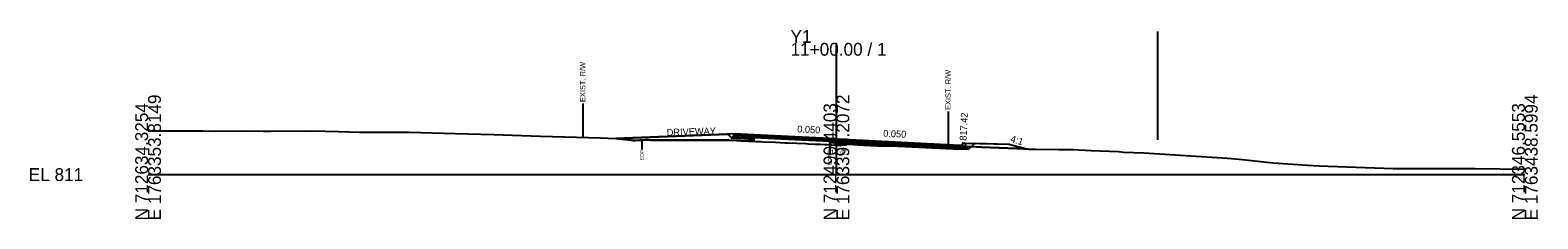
# Model space of a CAD drawing. Extents: x -26 to 1303, y -10 to 9524.
# Drawn here: x -25.7 to 302.8, y 990.3 to 1031.6 of the extents above; entities that cross this region are included whole.
import ezdxf

# ---------------------------------------------------------------- set-up
doc = ezdxf.new("R2010")
doc.units = 0
for name, color, linetype in [('Default', 7, 'Continuous'), ('Exist CMT Pavement', 7, 'Continuous'), ('Exist Cross Section Cell', 7, 'Continuous'), ('Exist XS Center Line Elevation Label', 7, 'Continuous'), ('Exist XS Ground Line', 7, 'Continuous'), ('Old_Level_10', 7, 'Continuous'), ('Prop CMT Conc Surface', 7, 'Continuous'), ('Prop CMT Concrete Structures', 7, 'Continuous'), ('Prop CMT Pvmt Course 1', 7, 'Continuous'), ('Prop CMT Pvmt Course 1 CG', 7, 'Continuous'), ('Prop CMT Pvmt Course 2', 7, 'Continuous'), ('Prop CMT Pvmt Course 3', 7, 'Continuous'), ('Prop CMT Pvmt Surface', 7, 'Continuous'), ('Prop CMT Pvmt Surface Shoulder', 7, 'Continuous'), ('Prop CMT Shld Paved Course 1', 7, 'Continuous'), ('Prop CMT Shld Paved Course 3', 7, 'Continuous'), ('Prop CMT Slope Grass', 7, 'Continuous'), ('Prop CMT Subgrade Earthwork', 7, 'Continuous'), ('Prop XS Earthwork Shape', 7, 'Continuous'), ('Prop XS Hydro Elevations', 7, 'Continuous'), ('Prop XS SE Text', 7, 'Continuous'), ('Prop XS Side Slope Text', 7, 'Continuous'), ('Prop XS Wedging', 7, 'Continuous')]:
    doc.layers.add(name, color=color, linetype=linetype)

msp = doc.modelspace()

# ---------------------------------------------------------------- linework, layer by layer
at = {"layer": 'Exist CMT Pavement'}
msp.add_lwpolyline([(131.98, 1007.27), (132.46, 1007.25), (133.52, 1007.19), (133.96, 1007.18), (136.69, 1007.08), (138.73, 1006.96), (139.32, 1006.93), (141.34, 1006.86), (143.34, 1006.76), (143.94, 1006.73), (145.36, 1006.67), (146.55, 1006.61), (147.47, 1006.56), (147.96, 1006.54), (148.58, 1006.5)], dxfattribs=at)
at = {"layer": 'Exist Cross Section Cell'}
for p, q in [((150, 1000), (150, 1028.77)), ((0, 1000), (150, 1000)), ((150, 1000), (300, 1000))]:
    msp.add_line(p, q, dxfattribs=at)
at = {"layer": 'Exist XS Ground Line'}
msp.add_lwpolyline([(0, 1009.59), (4.33, 1009.56), (11.92, 1009.57), (14.76, 1009.46), (21.53, 1009.52), (25.18, 1009.51), (26.71, 1009.48), (35.61, 1009.56), (41.49, 1009.41), (46.03, 1009.26), (56.46, 1009.28), (56.92, 1009.26), (66.89, 1008.98), (75.31, 1008.78), (85.54, 1008.41), (98.61, 1008), (101.92, 1007.89), (102.49, 1007.83), (103.14, 1007.76), (103.92, 1007.67), (105.28, 1007.48), (105.7, 1007.46), (106.17, 1007.45), (107.14, 1007.5), (107.62, 1007.55), (108.24, 1007.56), (108.98, 1007.56), (109.55, 1007.55), (110.06, 1007.55), (111.13, 1007.54), (112.67, 1007.53), (113.15, 1007.53), (114.77, 1007.55), (115.27, 1007.55), (117.17, 1007.51), (117.88, 1007.49), (119.18, 1007.5), (120.37, 1007.51), (121.25, 1007.52), (121.66, 1007.53), (123.21, 1007.51), (123.61, 1007.51), (125.7, 1007.5), (126.57, 1007.48), (128.31, 1007.42), (129.25, 1007.39), (130.91, 1007.33), (131.26, 1007.31), (132.46, 1007.25), (133.52, 1007.19), (133.96, 1007.18), (136.69, 1007.08), (138.73, 1006.96), (139.32, 1006.93), (141.34, 1006.86), (143.34, 1006.76), (143.94, 1006.73), (145.36, 1006.67), (146.55, 1006.61), (147.47, 1006.56), (147.96, 1006.54), (148.58, 1006.5), (148.91, 1006.49), (150, 1006.42), (150.9, 1006.37), (151.53, 1006.73), (155.89, 1006.4), (160.45, 1006.2), (165.64, 1006.32), (171.15, 1006.56), (174.52, 1006.4), (181.58, 1005.95), (189.3, 1005.66), (192, 1005.53), (193.48, 1005.58), (198.47, 1005.49), (201.53, 1005.49), (205.48, 1005.28), (211.45, 1005.03), (212.56, 1004.92), (216.99, 1004.73), (235.25, 1003.57), (237.75, 1003.37), (245.19, 1002.57), (252.66, 1002.05), (255.1, 1001.92), (271.34, 1001.31), (287.93, 1001.34), (288.7, 1001.34), (289.16, 1001.35), (300, 1001.2)], dxfattribs=at)
at = {"layer": 'Old_Level_10'}
for p, q in [((94.71, 1015.53), (94.71, 1008.12)), ((174.33, 1013.81), (174.33, 1006.41)), ((107.62, 1007.55), (107.62, 1005.5)), ((148.58, 1006.5), (148.58, 1004.45))]:
    msp.add_line(p, q, dxfattribs=at)
at = {"layer": 'Prop CMT Conc Surface'}
for points in [[(175.53, 1006.52), (177.53, 1006.42)], [(177.53, 1006.42), (177.55, 1006.92), (178.05, 1006.89)]]:
    msp.add_lwpolyline(points, dxfattribs=at)
at = {"layer": 'Prop CMT Concrete Structures'}
for points in [[(178.05, 1006.89), (178, 1005.91), (175.53, 1005.93)], [(175.53, 1005.93), (175.53, 1006.52)]]:
    msp.add_lwpolyline(points, dxfattribs=at)
at = {"layer": 'Prop CMT Pvmt Course 1'}
for points in [[(150, 1007.79), (132, 1008.69)], [(132, 1008.69), (132, 1008.44)], [(132, 1008.44), (150, 1007.54)], [(150, 1007.54), (150, 1007.79)], [(150, 1007.79), (175.46, 1006.52)], [(150, 1007.54), (150, 1007.79)], [(150, 1007.54), (150, 1007.54), (150, 1007.54)], [(175.46, 1006.27), (150, 1007.54)], [(150, 1007.54), (150, 1007.54), (150, 1007.54), (150, 1007.54), (150, 1007.54)], [(175.46, 1006.52), (175.46, 1006.27)], [(175.53, 1006.52), (175.53, 1006.27)], [(175.53, 1006.52), (175.53, 1006.27)]]:
    msp.add_lwpolyline(points, dxfattribs=at)
at = {"layer": 'Prop CMT Pvmt Course 1 CG'}
for points in [[(175.53, 1005.93), (178.5, 1005.91), (178.81, 1005.56)], [(178.81, 1005.56), (175.53, 1005.6)]]:
    msp.add_lwpolyline(points, dxfattribs=at)
at = {"layer": 'Prop CMT Pvmt Course 2'}
for points in [[(132, 1008.11), (150, 1007.21)], [(175.53, 1006.27), (175.53, 1005.93)], [(175.53, 1006.27), (175.53, 1005.93)]]:
    msp.add_lwpolyline(points, dxfattribs=at)
at = {"layer": 'Prop CMT Pvmt Course 3'}
for points in [[(132, 1008.44), (132, 1008.03)], [(150, 1007.21), (132, 1008.11)], [(148.58, 1007.2), (148.58, 1007.61)], [(150, 1007.54), (175.46, 1006.27)], [(150, 1007.13), (150, 1007.54)], [(175.46, 1005.94), (150, 1007.21)], [(175.46, 1006.27), (175.46, 1005.94)]]:
    msp.add_lwpolyline(points, dxfattribs=at)
at = {"layer": 'Prop CMT Pvmt Surface'}
for points in [[(150, 1007.79), (132, 1008.69)], [(150, 1007.79), (175.46, 1006.52)]]:
    msp.add_lwpolyline(points, dxfattribs=at)
at = {"layer": 'Prop CMT Pvmt Surface Shoulder'}
for points in [[(132, 1008.69), (128, 1008.89)], [(175.46, 1006.52), (175.53, 1006.52)]]:
    msp.add_lwpolyline(points, dxfattribs=at)
at = {"layer": 'Prop CMT Shld Paved Course 1'}
for points in [[(132, 1008.69), (128, 1008.89), (127.76, 1008.66)], [(127.76, 1008.66), (132, 1008.44)], [(132, 1008.44), (132, 1008.69)], [(175.46, 1006.27), (175.46, 1006.52)], [(175.46, 1006.52), (175.53, 1006.52)], [(175.53, 1006.27), (175.46, 1006.27)]]:
    msp.add_lwpolyline(points, dxfattribs=at)
at = {"layer": 'Prop CMT Shld Paved Course 3'}
for points in [[(127.76, 1008.66), (127.12, 1008.02)], [(132, 1008.44), (127.76, 1008.66)], [(127.36, 1008.01), (131.99, 1007.77)], [(127.44, 1008.34), (132, 1008.11)], [(132, 1008.11), (132, 1008.44)], [(175.46, 1005.94), (175.46, 1006.27)], [(175.46, 1006.27), (175.53, 1006.27)], [(175.46, 1005.94), (175.53, 1005.93)], [(175.46, 1005.6), (175.53, 1005.6)]]:
    msp.add_lwpolyline(points, dxfattribs=at)
at = {"layer": 'Prop CMT Slope Grass'}
for p, q in [((128, 1008.89), (101.95, 1007.89)), ((187.55, 1006.61), (191.81, 1005.54))]:
    msp.add_line(p, q, dxfattribs=at)
msp.add_lwpolyline([(178.05, 1006.89), (187.55, 1006.61)], dxfattribs=at)
at = {"layer": 'Prop CMT Subgrade Earthwork'}
for p, q in [((131.99, 1007.77), (127.12, 1008.02)), ((131.99, 1007.77), (131.98, 1007.27)), ((148.58, 1006.5), (148.58, 1006.94)), ((150, 1006.87), (148.58, 1006.94)), ((150, 1006.87), (175.46, 1005.6)), ((175.46, 1005.6), (175.53, 1005.6))]:
    msp.add_line(p, q, dxfattribs=at)
for points in [[(126.31, 1008.83), (127.12, 1008.02)], [(175.53, 1005.6), (178.81, 1005.56), (180.21, 1006.83)]]:
    msp.add_lwpolyline(points, dxfattribs=at)
at = {"layer": 'Prop XS Earthwork Shape'}
msp.add_line((220.02, 1007.6), (220.02, 1031.27), dxfattribs=at)
for points in [[(131.99, 1007.77), (131.98, 1007.27), (131.26, 1007.31), (130.91, 1007.33), (129.25, 1007.39), (128.31, 1007.42), (126.57, 1007.48), (125.7, 1007.5), (123.61, 1007.51), (123.21, 1007.51), (121.66, 1007.53), (121.25, 1007.52), (120.37, 1007.51), (119.18, 1007.5), (117.88, 1007.49), (117.17, 1007.51), (115.27, 1007.55), (114.77, 1007.55), (113.15, 1007.53), (112.67, 1007.53), (111.13, 1007.54), (110.06, 1007.55), (109.55, 1007.55), (108.98, 1007.56), (108.24, 1007.56), (107.62, 1007.55), (107.14, 1007.5), (106.17, 1007.45), (105.7, 1007.46), (105.28, 1007.48), (103.92, 1007.67), (103.14, 1007.76), (102.49, 1007.83), (101.95, 1007.89), (126.31, 1008.83), (127.12, 1008.02)], [(150, 1006.87), (148.58, 1006.94), (148.58, 1006.5), (148.91, 1006.49), (150, 1006.42), (150.9, 1006.37), (151.53, 1006.73), (155.89, 1006.4), (160.45, 1006.2), (162.54, 1006.25)], [(175.46, 1005.6), (175.53, 1005.6), (178.81, 1005.56), (179.39, 1006.09), (174.52, 1006.4), (171.15, 1006.56), (165.64, 1006.32), (162.54, 1006.25)], [(187.55, 1006.61), (191.81, 1005.54), (189.3, 1005.66), (181.58, 1005.95), (179.39, 1006.09), (180.21, 1006.83)]]:
    msp.add_lwpolyline(points, close=True, dxfattribs=at)
at = {"layer": 'Prop XS Wedging'}
for p, q in [((132, 1007.78), (131.98, 1007.27)), ((131.98, 1007.27), (132.46, 1007.25)), ((132, 1008.11), (132, 1007.78)), ((132.46, 1007.25), (133.52, 1007.19)), ((133.52, 1007.19), (133.96, 1007.18)), ((133.96, 1007.18), (136.69, 1007.08)), ((136.69, 1007.08), (138.73, 1006.96)), ((138.73, 1006.96), (139.32, 1006.93)), ((143.34, 1006.76), (143.94, 1006.73)), ((143.94, 1006.73), (145.36, 1006.67)), ((145.36, 1006.67), (146.55, 1006.61)), ((147.96, 1006.54), (148.58, 1006.5)), ((148.58, 1007.28), (148.58, 1007.61)), ((148.58, 1006.95), (148.58, 1007.28)), ((148.58, 1007.28), (148.58, 1007.28)), ((148.58, 1006.5), (148.58, 1006.95)), ((148.58, 1006.95), (148.58, 1006.95))]:
    msp.add_line(p, q, dxfattribs=at)
for points in [[(148.58, 1007.61), (132, 1008.44), (132, 1008.11)], [(139.32, 1006.93), (141.34, 1006.86), (143.34, 1006.76)], [(146.55, 1006.61), (147.47, 1006.56), (147.96, 1006.54)]]:
    msp.add_lwpolyline(points, dxfattribs=at)

# ---------------------------------------------------------------- texts
at = {"layer": 'Default'}
msp.add_text('-', height=0.0001, dxfattribs=at).set_placement((0, 1000))
at = {"layer": 'Exist Cross Section Cell'}
for s, p in [('Y1', (140, 1028.77)), ('11+00.00 / 1', (140, 1025.97)), ('EL 811', (-26, 998.6))]:
    msp.add_text(s, height=2.8, dxfattribs=at).set_placement(p)
for s, p in [('N 712634.3254', (0, 990)), ('E 1763353.8149', (2.8, 990)), ('N 712490.4403', (150, 990)), ('E 1763396.2072', (152.8, 990)), ('N 712346.5553', (300, 990)), ('E 1763438.5994', (302.8, 990))]:
    msp.add_text(s, height=2.8, rotation=90, dxfattribs=at).set_placement(p)
at = {"layer": 'Exist XS Center Line Elevation Label'}
msp.add_text('817.42', height=1, dxfattribs=at).set_placement((148.01, 1004.42))
at = {"layer": 'Old_Level_10'}
for s, height, p in [('EXIST. R/W', 1.181, (95.3, 1015.83)), ('EXIST. R/W', 1.181, (174.92, 1014.11)), ('EOP', 0.787, (108.02, 1003.1)), ('EOP', 0.787, (148.98, 1002.06))]:
    msp.add_text(s, height=height, rotation=90, dxfattribs=at).set_placement(p)
at = {"layer": 'Prop XS Hydro Elevations'}
msp.add_text('817.42', height=1.5, rotation=87.1376, dxfattribs=at).set_placement((178.33, 1007.37))
at = {"layer": 'Prop XS SE Text'}
for p in [(141.43, 1009.22), (160.16, 1008.29)]:
    msp.add_text('0.050', height=1.5, rotation=357.1376, dxfattribs=at).set_placement(p)
at = {"layer": 'Prop XS Side Slope Text'}
for s, rotation, p in [('DRIVEWAY', 1.9648, (113.05, 1008.45)), ('4:1', 343.1014, (187.8, 1007.17))]:
    msp.add_text(s, height=1.5, rotation=rotation, dxfattribs=at).set_placement(p)

doc.saveas('drawing.dxf')
